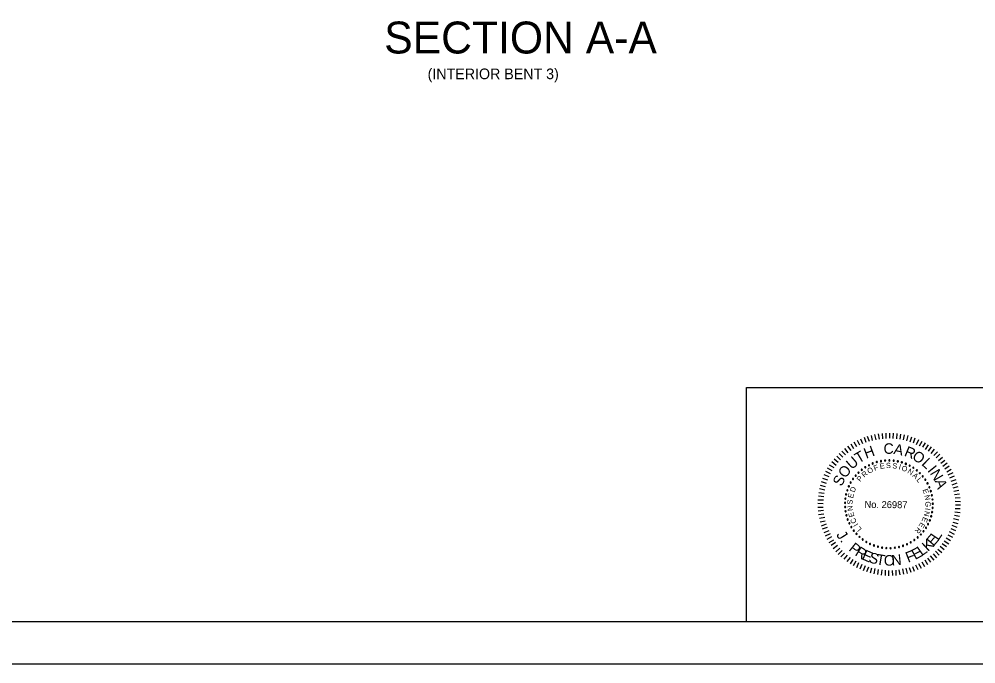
# Model space of a CAD drawing. Extents: x 1970675.2 to 1970711.3, y 796145.2 to 796167.2.
# Drawn here: x 1970689.32 to 1970700.57, y 796145.25 to 796152.83 of the extents above; entities that cross this region are included whole.
import ezdxf

# ---------------------------------------------------------------- set-up
doc = ezdxf.new("R2010")
doc.units = 0
for name, color, linetype in [('BR_BORDER LINES', 7, 'Continuous'), ('BR_TEXT', 7, 'Continuous'), ('Level 31', 7, 'Continuous')]:
    doc.layers.add(name, color=color, linetype=linetype)

msp = doc.modelspace()

# ---------------------------------------------------------------- linework, layer by layer
at = {"layer": 'BR_BORDER LINES'}
for p, q in [((1970697.87, 796148.496), (1970703.236, 796148.496)), ((1970697.87, 796145.746), (1970697.87, 796148.496)), ((1970677.07, 796145.746), (1970710.736, 796145.746))]:
    msp.add_line(p, q, dxfattribs=at)
at = {"layer": 'BR_TEXT'}
for p, q in [((1970699.351, 796147.872), (1970699.338, 796147.933)), ((1970699.392, 796147.882), (1970699.378, 796147.941)), ((1970699.432, 796147.889), (1970699.423, 796147.95)), ((1970699.472, 796147.893), (1970699.468, 796147.954)), ((1970699.511, 796147.896), (1970699.512, 796147.96)), ((1970699.553, 796147.898), (1970699.554, 796147.96)), ((1970699.595, 796147.895), (1970699.597, 796147.959)), ((1970699.635, 796147.892), (1970699.64, 796147.953)), ((1970699.674, 796147.887), (1970699.685, 796147.948)), ((1970699.714, 796147.879), (1970699.728, 796147.938)), ((1970699.755, 796147.869), (1970699.771, 796147.93)), ((1970699.13, 796147.774), (1970699.099, 796147.829)), ((1970699.165, 796147.798), (1970699.135, 796147.852)), ((1970699.2, 796147.816), (1970699.174, 796147.872)), ((1970699.237, 796147.833), (1970699.213, 796147.889)), ((1970699.275, 796147.85), (1970699.255, 796147.908)), ((1970699.315, 796147.862), (1970699.293, 796147.92)), ((1970699.792, 796147.858), (1970699.814, 796147.915)), ((1970699.832, 796147.845), (1970699.854, 796147.903)), ((1970699.867, 796147.827), (1970699.895, 796147.883)), ((1970699.903, 796147.81), (1970699.935, 796147.866)), ((1970699.941, 796147.792), (1970699.973, 796147.845)), ((1970699.974, 796147.767), (1970700.008, 796147.821)), ((1970699.003, 796147.676), (1970698.959, 796147.72)), ((1970699.032, 796147.703), (1970698.991, 796147.748)), ((1970699.065, 796147.728), (1970699.025, 796147.778)), ((1970699.099, 796147.753), (1970699.06, 796147.804)), ((1970700.008, 796147.746), (1970700.044, 796147.796)), ((1970700.04, 796147.72), (1970700.081, 796147.769)), ((1970700.071, 796147.695), (1970700.115, 796147.739)), ((1970700.1, 796147.667), (1970700.143, 796147.71)), ((1970698.922, 796147.58), (1970698.873, 796147.62)), ((1970698.948, 796147.614), (1970698.899, 796147.653)), ((1970698.973, 796147.645), (1970698.93, 796147.688)), ((1970700.128, 796147.636), (1970700.175, 796147.677)), ((1970700.155, 796147.604), (1970700.201, 796147.642)), ((1970700.179, 796147.57), (1970700.228, 796147.609)), ((1970698.859, 796147.481), (1970698.802, 796147.508)), ((1970698.876, 796147.515), (1970698.822, 796147.547)), ((1970698.901, 796147.551), (1970698.847, 796147.584)), ((1970700.201, 796147.541), (1970700.253, 796147.573)), ((1970700.223, 796147.504), (1970700.276, 796147.535)), ((1970700.24, 796147.469), (1970700.298, 796147.496)), ((1970698.812, 796147.365), (1970698.75, 796147.388)), ((1970698.824, 796147.405), (1970698.766, 796147.427)), ((1970698.841, 796147.444), (1970698.784, 796147.469)), ((1970700.258, 796147.432), (1970700.315, 796147.457)), ((1970700.275, 796147.393), (1970700.332, 796147.414)), ((1970700.288, 796147.353), (1970700.346, 796147.375)), ((1970698.781, 796147.251), (1970698.721, 796147.259)), ((1970698.792, 796147.287), (1970698.729, 796147.303)), ((1970698.799, 796147.329), (1970698.738, 796147.344)), ((1970700.298, 796147.317), (1970700.359, 796147.331)), ((1970700.307, 796147.275), (1970700.367, 796147.29)), ((1970698.774, 796147.171), (1970698.709, 796147.171)), ((1970698.777, 796147.21), (1970698.715, 796147.217)), ((1970700.315, 796147.239), (1970700.374, 796147.246)), ((1970700.321, 796147.197), (1970700.382, 796147.204)), ((1970700.323, 796147.158), (1970700.383, 796147.157)), ((1970698.772, 796147.129), (1970698.709, 796147.13)), ((1970698.773, 796147.086), (1970698.709, 796147.085)), ((1970698.775, 796147.048), (1970698.714, 796147.041)), ((1970700.32, 796147.035), (1970700.381, 796147.027)), ((1970700.322, 796147.074), (1970700.382, 796147.071)), ((1970700.325, 796147.117), (1970700.386, 796147.116)), ((1970698.779, 796147.007), (1970698.718, 796146.998)), ((1970698.789, 796146.967), (1970698.727, 796146.954)), ((1970698.796, 796146.925), (1970698.735, 796146.911)), ((1970700.295, 796146.913), (1970700.355, 796146.897)), ((1970700.304, 796146.955), (1970700.364, 796146.94)), ((1970700.313, 796146.994), (1970700.372, 796146.984)), ((1970698.808, 796146.888), (1970698.746, 796146.867)), ((1970698.819, 796146.849), (1970698.761, 796146.828)), ((1970698.836, 796146.812), (1970698.778, 796146.785)), ((1970700.253, 796146.801), (1970700.309, 796146.773)), ((1970700.27, 796146.837), (1970700.327, 796146.815)), ((1970700.284, 796146.876), (1970700.342, 796146.854)), ((1970698.853, 796146.776), (1970698.796, 796146.746)), ((1970698.87, 796146.739), (1970698.816, 796146.708)), ((1970698.894, 796146.702), (1970698.839, 796146.671)), ((1970700.194, 796146.691), (1970700.246, 796146.659)), ((1970700.216, 796146.728), (1970700.269, 796146.696)), ((1970700.235, 796146.765), (1970700.292, 796146.734)), ((1970698.915, 796146.673), (1970698.865, 796146.636)), ((1970698.94, 796146.639), (1970698.89, 796146.6)), ((1970698.965, 796146.605), (1970698.921, 796146.564)), ((1970698.994, 796146.579), (1970698.949, 796146.534)), ((1970700.119, 796146.596), (1970700.166, 796146.554)), ((1970700.147, 796146.629), (1970700.193, 796146.589)), ((1970700.171, 796146.662), (1970700.22, 796146.625)), ((1970699.023, 796146.549), (1970698.98, 796146.503)), ((1970699.055, 796146.523), (1970699.014, 796146.476)), ((1970699.088, 796146.497), (1970699.049, 796146.449)), ((1970699.119, 796146.475), (1970699.088, 796146.423)), ((1970699.964, 796146.468), (1970699.997, 796146.416)), ((1970699.997, 796146.489), (1970700.033, 796146.441)), ((1970700.03, 796146.515), (1970700.07, 796146.467)), ((1970700.062, 796146.54), (1970700.104, 796146.494)), ((1970700.09, 796146.57), (1970700.133, 796146.524)), ((1970699.154, 796146.453), (1970699.123, 796146.399)), ((1970699.188, 796146.433), (1970699.161, 796146.377)), ((1970699.225, 796146.415), (1970699.201, 796146.36)), ((1970699.263, 796146.398), (1970699.242, 796146.341)), ((1970699.303, 796146.385), (1970699.28, 796146.327)), ((1970699.339, 796146.373), (1970699.325, 796146.314)), ((1970699.38, 796146.366), (1970699.365, 796146.304)), ((1970699.419, 796146.354), (1970699.409, 796146.296)), ((1970699.661, 796146.352), (1970699.671, 796146.294)), ((1970699.702, 796146.363), (1970699.715, 796146.301)), ((1970699.743, 796146.37), (1970699.758, 796146.31)), ((1970699.78, 796146.381), (1970699.801, 796146.323)), ((1970699.82, 796146.393), (1970699.841, 796146.336)), ((1970699.856, 796146.41), (1970699.883, 796146.354)), ((1970699.892, 796146.427), (1970699.922, 796146.371)), ((1970699.93, 796146.446), (1970699.961, 796146.392)), ((1970699.459, 796146.35), (1970699.454, 796146.288)), ((1970699.498, 796146.347), (1970699.498, 796146.285)), ((1970699.54, 796146.344), (1970699.54, 796146.283)), ((1970699.582, 796146.346), (1970699.584, 796146.284)), ((1970699.623, 796146.348), (1970699.626, 796146.286))]:
    msp.add_line(p, q, dxfattribs=at)
for centre, start, end in [((1970699.309, 796147.581), 27.2191, 207.2191), ((1970699.354, 796147.602), 21.6807, 201.6807), ((1970699.354, 796147.602), 201.6807, 21.6807), ((1970699.401, 796147.618), 16.1422, 196.1422), ((1970699.401, 796147.618), 196.1422, 16.1422), ((1970699.45, 796147.629), 10.6038, 190.6038), ((1970699.45, 796147.629), 190.6038, 10.6038), ((1970699.499, 796147.636), 5.0653, 185.0653), ((1970699.499, 796147.636), 185.0653, 5.0653), ((1970699.549, 796147.638), 359.5268, 179.5268), ((1970699.549, 796147.638), 179.5268, 359.5268), ((1970699.599, 796147.635), 353.9884, 173.9884), ((1970699.599, 796147.635), 173.9884, 353.9884), ((1970699.648, 796147.627), 348.4499, 168.4499), ((1970699.648, 796147.627), 168.4499, 348.4499), ((1970699.696, 796147.615), 342.9114, 162.9114), ((1970699.696, 796147.615), 162.9114, 342.9114), ((1970699.743, 796147.598), 337.373, 157.373), ((1970699.743, 796147.598), 157.373, 337.373), ((1970699.187, 796147.495), 43.8345, 223.8345), ((1970699.187, 796147.495), 223.8345, 43.8345), ((1970699.225, 796147.528), 38.2961, 218.2961), ((1970699.225, 796147.528), 218.2961, 38.2961), ((1970699.265, 796147.557), 32.7576, 212.7576), ((1970699.265, 796147.557), 212.7576, 32.7576), ((1970699.309, 796147.581), 207.2191, 27.2191), ((1970699.788, 796147.576), 151.8345, 331.8345), ((1970699.788, 796147.576), 331.8345, 151.8345), ((1970699.831, 796147.551), 146.2961, 326.2961), ((1970699.831, 796147.551), 326.2961, 146.2961), ((1970699.871, 796147.521), 140.7576, 320.7576), ((1970699.871, 796147.521), 320.7576, 140.7576), ((1970699.907, 796147.488), 135.2191, 315.2191), ((1970699.907, 796147.488), 315.2191, 135.2191), ((1970699.095, 796147.378), 60.4499, 240.4499), ((1970699.095, 796147.378), 240.4499, 60.4499), ((1970699.122, 796147.42), 54.9114, 234.9114), ((1970699.122, 796147.42), 234.9114, 54.9114), ((1970699.153, 796147.459), 49.373, 229.373), ((1970699.153, 796147.459), 229.373, 49.373), ((1970699.941, 796147.451), 129.6807, 309.6807), ((1970699.941, 796147.451), 309.6807, 129.6807), ((1970699.971, 796147.411), 124.1422, 304.1422), ((1970699.971, 796147.411), 304.1422, 124.1422), ((1970699.997, 796147.368), 118.6038, 298.6038), ((1970699.997, 796147.368), 298.6038, 118.6038), ((1970699.055, 796147.287), 71.5268, 251.5268), ((1970699.055, 796147.287), 251.5268, 71.5268), ((1970699.073, 796147.333), 65.9884, 245.9884), ((1970699.073, 796147.333), 245.9884, 65.9884), ((1970700.018, 796147.323), 113.0653, 293.0653), ((1970700.018, 796147.323), 293.0653, 113.0653), ((1970700.036, 796147.277), 107.5268, 287.5268), ((1970700.036, 796147.277), 287.5268, 107.5268), ((1970699.028, 796147.14), 88.1422, 268.1422), ((1970699.032, 796147.19), 82.6038, 262.6038), ((1970699.028, 796147.14), 268.1422, 88.1422), ((1970699.032, 796147.19), 262.6038, 82.6038), ((1970699.041, 796147.239), 77.0653, 257.0653), ((1970699.041, 796147.239), 257.0653, 77.0653), ((1970700.048, 796147.228), 101.9884, 281.9884), ((1970700.048, 796147.228), 281.9884, 101.9884), ((1970700.056, 796147.179), 96.4499, 276.4499), ((1970700.056, 796147.179), 276.4499, 96.4499), ((1970699.029, 796147.09), 93.6807, 273.6807), ((1970699.034, 796147.041), 99.2191, 279.2191), ((1970699.029, 796147.09), 273.6807, 93.6807), ((1970699.034, 796147.041), 279.2191, 99.2191), ((1970700.051, 796147.03), 79.8345, 259.8345), ((1970700.057, 796147.08), 85.373, 265.373), ((1970700.051, 796147.03), 259.8345, 79.8345), ((1970700.059, 796147.129), 90.9114, 270.9114), ((1970700.057, 796147.08), 265.373, 85.373), ((1970700.059, 796147.129), 270.9114, 90.9114), ((1970699.045, 796146.992), 104.7576, 284.7576), ((1970699.045, 796146.992), 284.7576, 104.7576), ((1970699.059, 796146.944), 110.2961, 290.2961), ((1970699.059, 796146.944), 290.2961, 110.2961), ((1970700.024, 796146.934), 68.7576, 248.7576), ((1970700.024, 796146.934), 248.7576, 68.7576), ((1970700.04, 796146.982), 74.2961, 254.2961), ((1970700.04, 796146.982), 254.2961, 74.2961), ((1970699.079, 796146.898), 115.8345, 295.8345), ((1970699.079, 796146.898), 295.8345, 115.8345), ((1970699.103, 796146.855), 121.373, 301.373), ((1970699.103, 796146.855), 301.373, 121.373), ((1970699.131, 796146.813), 126.9114, 306.9114), ((1970699.131, 796146.813), 306.9114, 126.9114), ((1970699.95, 796146.805), 52.1422, 232.1422), ((1970699.95, 796146.805), 232.1422, 52.1422), ((1970699.979, 796146.846), 57.6807, 237.6807), ((1970699.979, 796146.846), 237.6807, 57.6807), ((1970700.003, 796146.889), 63.2191, 243.2191), ((1970700.003, 796146.889), 243.2191, 63.2191), ((1970699.162, 796146.775), 132.4499, 312.4499), ((1970699.162, 796146.775), 312.4499, 132.4499), ((1970699.198, 796146.74), 137.9884, 317.9884), ((1970699.198, 796146.74), 317.9884, 137.9884), ((1970699.236, 796146.708), 143.5268, 323.5268), ((1970699.236, 796146.708), 323.5268, 143.5268), ((1970699.842, 796146.702), 35.5268, 215.5268), ((1970699.842, 796146.702), 215.5268, 35.5268), ((1970699.882, 796146.733), 41.0653, 221.0653), ((1970699.882, 796146.733), 221.0653, 41.0653), ((1970699.918, 796146.767), 46.6038, 226.6038), ((1970699.918, 796146.767), 226.6038, 46.6038), ((1970699.278, 796146.68), 149.0653, 329.0653), ((1970699.278, 796146.68), 329.0653, 149.0653), ((1970699.321, 796146.657), 154.6038, 334.6038), ((1970699.321, 796146.657), 334.6038, 154.6038), ((1970699.367, 796146.638), 160.1422, 340.1422), ((1970699.367, 796146.638), 340.1422, 160.1422), ((1970699.415, 796146.623), 345.6807, 165.6807), ((1970699.415, 796146.623), 165.6807, 345.6807), ((1970699.464, 796146.613), 351.2191, 171.2191), ((1970699.464, 796146.613), 171.2191, 351.2191), ((1970699.513, 796146.607), 356.7576, 176.7576), ((1970699.513, 796146.607), 176.7576, 356.7576), ((1970699.563, 796146.607), 2.2961, 182.2961), ((1970699.563, 796146.607), 182.2961, 2.2961), ((1970699.613, 796146.611), 7.8345, 187.8345), ((1970699.613, 796146.611), 187.8345, 7.8345), ((1970699.662, 796146.62), 13.373, 193.373), ((1970699.662, 796146.62), 193.373, 13.373), ((1970699.71, 796146.634), 18.9114, 198.9114), ((1970699.71, 796146.634), 198.9114, 18.9114), ((1970699.756, 796146.652), 24.4499, 204.4499), ((1970699.756, 796146.652), 204.4499, 24.4499), ((1970699.8, 796146.675), 29.9884, 209.9884), ((1970699.8, 796146.675), 209.9884, 29.9884)]:
    msp.add_arc(centre, 0.00701, start, end, dxfattribs=at)
at = {"layer": 'Level 31'}
msp.add_lwpolyline([(1970675.236, 796145.246), (1970711.236, 796145.246), (1970711.236, 796167.246), (1970675.236, 796167.246)], close=True, dxfattribs=at)

# ---------------------------------------------------------------- texts
at = {"layer": 'BR_TEXT'}
msp.add_text('SECTION A-A', height=0.375, dxfattribs=at).set_placement((1970693.613, 796152.422))
for s, height, rotation, p in [('(INTERIOR BENT 3)', 0.125, 360, (1970694.123, 796152.12)), ('C', 0.124, 359.5482, (1970699.48, 796147.716)), ('A', 0.124, 348.1981, (1970699.592, 796147.716)), ('T', 0.124, 30.4992, (1970699.188, 796147.6)), ('H', 0.124, 20.3637, (1970699.276, 796147.657)), ('R', 0.124, 337.4344, (1970699.715, 796147.696)), ('O', 0.124, 326.5869, (1970699.807, 796147.66)), ('U', 0.124, 40.8022, (1970699.107, 796147.525)), ('F', 0.0622, 20.6127, (1970699.377, 796147.514)), ('E', 0.0622, 11.4103, (1970699.442, 796147.536)), ('S', 0.0622, 2.208, (1970699.51, 796147.547)), ('S', 0.0622, 352.6608, (1970699.581, 796147.547)), ('I', 0.0622, 343.1136, (1970699.652, 796147.535)), ('L', 0.124, 315.9488, (1970699.92, 796147.592)), ('O', 0.124, 52.0267, (1970699.032, 796147.421)), ('R', 0.0622, 40.3949, (1970699.254, 796147.434)), ('O', 0.0622, 30.8477, (1970699.31, 796147.478)), ('O', 0.0622, 338.4392, (1970699.685, 796147.525)), ('N', 0.0622, 328.2042, (1970699.755, 796147.493)), ('A', 0.0622, 318.657, (1970699.814, 796147.453)), ('I', 0.124, 308.6613, (1970699.991, 796147.518)), ('N', 0.124, 300.7037, (1970700.022, 796147.488)), ('S', 0.124, 63.2511, (1970698.987, 796147.325)), ('P', 0.0622, 49.9421, (1970699.206, 796147.382)), ('L', 0.0622, 309.4546, (1970699.863, 796147.406)), ('A', 0.124, 289.4792, (1970700.081, 796147.395)), ('E', 0.0622, 78.2388, (1970699.122, 796147.19)), ('D', 0.0622, 69.0364, (1970699.139, 796147.257)), ('E', 0.0622, 291.049, (1970699.937, 796147.291)), ('S', 0.0622, 87.786, (1970699.116, 796147.119)), ('No. 26987', 0.0817, 359.5268, (1970699.257, 796147.08)), ('N', 0.0622, 281.8466, (1970699.96, 796147.226)), ('G', 0.0622, 272.2995, (1970699.971, 796147.155)), ('N', 0.0622, 97.3332, (1970699.122, 796147.048)), ('E', 0.0622, 106.5355, (1970699.14, 796146.981)), ('N', 0.0622, 257.7339, (1970699.966, 796147.047)), ('I', 0.0622, 262.4084, (1970699.971, 796147.081)), ('C', 0.0622, 116.4266, (1970699.169, 796146.914)), ('E', 0.0622, 248.1867, (1970699.948, 796146.978)), ('J', 0.124, 302.9559, (1970698.92, 796146.763)), ('I', 0.0622, 121.1011, (1970699.187, 796146.884)), ('L', 0.0622, 129.9595, (1970699.228, 796146.832)), ('R', 0.0622, 229.782, (1970699.883, 796146.858)), ('E', 0.0622, 238.9844, (1970699.92, 796146.915)), ('.', 0.124, 309.3974, (1970698.964, 796146.695)), ('K', 0.124, 42.3031, (1970700.001, 796146.561)), ('E', 0.124, 49.3639, (1970700.066, 796146.621)), ('L', 0.124, 56.4247, (1970700.124, 796146.689)), ('P', 0.124, 321.1035, (1970699.063, 796146.586)), ('R', 0.124, 328.5359, (1970699.136, 796146.528)), ('E', 0.124, 335.9684, (1970699.216, 796146.48)), ('F', 0.124, 21.1206, (1970699.768, 796146.435)), ('E', 0.124, 28.1814, (1970699.851, 796146.467)), ('L', 0.124, 35.2422, (1970699.929, 796146.51)), ('S', 0.124, 343.0292, (1970699.297, 796146.444)), ('T', 0.124, 350.4617, (1970699.387, 796146.418)), ('O', 0.124, 358.1419, (1970699.482, 796146.403)), ('N', 0.124, 5.8221, (1970699.579, 796146.401))]:
    msp.add_text(s, height=height, rotation=rotation, dxfattribs=at).set_placement(p)

doc.saveas('drawing.dxf')
